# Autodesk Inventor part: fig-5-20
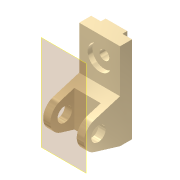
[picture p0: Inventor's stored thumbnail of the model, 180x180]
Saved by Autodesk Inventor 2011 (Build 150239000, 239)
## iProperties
Shininess: 65.0
Angle Display Precision: 2
Document Length Units: 11269
Document Angle Units: 11279
Document Time Units: 11290
Document Mass Units: 11283
Document Length Units Precision: 3
Document Angle Units Precision: 2
Compacted: False
Created: 2001-11
Part Number: fig-5-20
Document SubType Name: Modeling
Designer: Renu Muthoo
Density: 1 g/cm^3
Density: 0.0
Volumn: 0.0
Area: 0.0
PropertySet Name: Model Information
Control State: 0
Master: False
Checked Out: False
Author: Renu Muthoo
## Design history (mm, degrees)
node "Sketch1"
sketch "Sketch2"
  geometry: L1 (33.257, 104.664)-(33.257, -75.336); L2 (33.257, -75.336)-(8.257, -75.336); L3 (8.257, -75.336)-(-45.451, -59.045); L4 (-45.451, -1.628)-(8.257, 14.664); L5 (8.257, 14.664)-(8.257, 104.664); L6 (8.257, 104.664)-(33.257, 104.664); C1 r 15 at (-36.743, -30.336); A1 r 30 centre (-36.743, -30.336) between (-45.451, -1.628) and (-45.451, -59.045)
  constraints: 12 end point, 2 centre point, 2 equal length, 2 parallel, 2 point on circle, 2 tangent, 1 coincident, 1 perpendicular, 1 vertical
  dimensions: "d0" = 180 distance of L1.start L1.end; "d1" = 30 radius of A1; "d2" = 25 distance of L5.end L1.start; "d3" = 45 distance from line of L2 A1.centre; "d4" = 70 distance from line of L1 A1.centre; "d5" = 30 diameter of C1
extrude "Extrusion1" new body sketch "Sketch2" distance "d6" = 85; taper "d7" = 0 deg
workplane "Work Plane1"
sketch "Sketch3"
  geometry: L1 (15, 62.364)-(70, 62.364); L2 (70, 62.364)-(70, -52.386); L3 (70, -52.386)-(15, -52.386); L4 (15, -52.386)-(15, 62.364); L5 (0, -45)-(0, -28.708) reference
  constraints: 8 end point, 2 parallel, 1 horizontal, 1 perpendicular
  dimensions: "d8" = 55 distance of L1.start L1.end; "d9" = 15 distance between parallel lines of L5 L4
extrude "Extrusion2" cut sketch "Sketch3" distance "d10" = 50; taper "d11" = 0 deg
sketch "Sketch4"
  geometry: L1 (0, 25)-(85, 25) reference; L2 (0, 0)-(0, 25) reference; L3 (20, 25)-(65, 25); L4 (65, 25)-(65, 35); L5 (65, 35)-(20, 35); L6 (20, 35)-(20, 25)
  constraints: 8 end point, 2 parallel, 1 horizontal, 1 perpendicular, 1 point on line
  dimensions: "d12" = 45 distance of L4.end L5.end; "d13" = 10 distance of L3.end L4.end; "d14" = 20 distance between parallel lines of L2 L6
extrude "Extrusion3" join sketch "Sketch4" stored distance "d15" = 50; taper "d16" = 0 deg
sketch "Sketch5"
  geometry: L1 (85, 0)-(85, 90) reference; L2 (0, 90)-(85, 90) reference; 1 further point
  dimensions: "d17" = 42 distance from line of L2 point (42.5, 48); "d18" = 42.5 distance from line of L1 point (42.5, 48)
hole "Hole1" sketch "Sketch5" at (42.5, 48) diameter "d19" = 20; stored, may be unused: countersink angle "d23" = 82 deg, drill point angle "d25" = 118 deg; dims "d20" = 6, "d21" = 50, "d22" = 10, "d24" = 8
workplane "Work Plane10"
body "Solid1"
